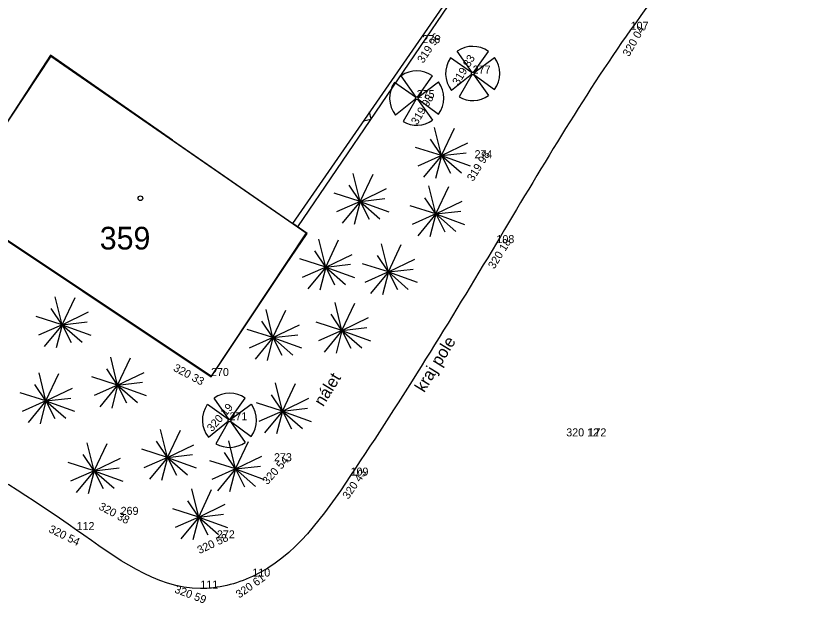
# Model space of a CAD drawing. Extents: x -742884 to -742543, y -1054677 to -1054433.
# Drawn here: x -742676.68 to -742647.31, y -1054570.62 to -1054548.61 of the extents above; entities that cross this region are included whole.
import ezdxf

# ---------------------------------------------------------------- set-up
doc = ezdxf.new("R2010")
doc.units = 0
for name, color, linetype in [('Vrstva 1', 7, 'Continuous'), ('Vrstva 10', 7, 'Continuous'), ('Vrstva 11', 7, 'Continuous'), ('Vrstva 15', 7, 'Continuous'), ('Vrstva 2', 7, 'Continuous'), ('Vrstva 3', 7, 'Continuous'), ('Vrstva 5', 7, 'Continuous'), ('Vrstva 50', 7, 'Continuous'), ('Vrstva 6', 7, 'Continuous')]:
    doc.layers.add(name, color=color, linetype=linetype)

# ---------------------------------------------------------------- blocks, each defined once
blk = doc.blocks.new('Z15')
at = {"layer": 'Vrstva 2'}
for p, q in [((-10, 2), (-8, 6)), ((-10, -2), (-10, 2)), ((-8, 6), (-6, 8)), ((-6, 8), (-2, 10)), ((-2, 10), (2, 10)), ((2, 10), (6, 8)), ((6, 8), (8, 6)), ((8, 6), (10, 2)), ((10, 2), (10, -2)), ((-8, -6), (-10, -2)), ((-6, -8), (-8, -6)), ((-2, -10), (-6, -8)), ((2, -10), (-2, -10)), ((6, -8), (2, -10)), ((8, -6), (6, -8)), ((10, -2), (8, -6))]:
    blk.add_line(p, q, dxfattribs=at)

msp = doc.modelspace()

# ---------------------------------------------------------------- linework, layer by layer
at = {"layer": 'Vrstva 1'}
for p, q in [((-742653.63, -1054549.14), (-742653.63, -1054549.14)), ((-742661.44, -1054549.64), (-742661.44, -1054549.64)), ((-742659.55, -1054550.78), (-742659.55, -1054550.78)), ((-742661.65, -1054551.7), (-742661.65, -1054551.7)), ((-742659.48, -1054553.95), (-742659.48, -1054553.95)), ((-742658.66, -1054557.13), (-742658.66, -1054557.13)), ((-742669.36, -1054562.11), (-742669.36, -1054562.11)), ((-742668.67, -1054563.77), (-742668.67, -1054563.77)), ((-742655.21, -1054564.37), (-742655.21, -1054564.37)), ((-742667, -1054565.3), (-742667, -1054565.3)), ((-742664.13, -1054565.84), (-742664.13, -1054565.84)), ((-742672.75, -1054567.31), (-742672.75, -1054567.31)), ((-742674.4, -1054567.88), (-742674.4, -1054567.88)), ((-742669.14, -1054568.19), (-742669.14, -1054568.19)), ((-742667.81, -1054569.62), (-742667.81, -1054569.62)), ((-742669.76, -1054570.07), (-742669.76, -1054570.07))]:
    msp.add_line(p, q, dxfattribs=at)
at = {"layer": 'Vrstva 10'}
for p, q in [((-742659.574, -1054550.74), (-742660.128, -1054549.943)), ((-742659.52, -1054550.74), (-742658.959, -1054549.949)), ((-742659.59, -1054550.746), (-742660.378, -1054550.19)), ((-742659.512, -1054550.751), (-742658.732, -1054550.174)), ((-742659.591, -1054550.815), (-742660.34, -1054551.417)), ((-742659.58, -1054550.825), (-742660.061, -1054551.656)), ((-742659.516, -1054550.82), (-742658.958, -1054551.607)), ((-742659.506, -1054550.809), (-742658.732, -1054551.382)), ((-742661.69, -1054551.666), (-742662.478, -1054551.11)), ((-742661.674, -1054551.66), (-742662.228, -1054550.863)), ((-742661.62, -1054551.66), (-742661.059, -1054550.869)), ((-742661.612, -1054551.671), (-742660.832, -1054551.094)), ((-742661.691, -1054551.735), (-742662.44, -1054552.337)), ((-742661.616, -1054551.74), (-742661.058, -1054552.527)), ((-742661.606, -1054551.729), (-742660.832, -1054552.302)), ((-742661.68, -1054551.745), (-742662.161, -1054552.576)), ((-742660.722, -1054553.85), (-742660.979, -1054552.8)), ((-742660.722, -1054553.85), (-742660.237, -1054552.825)), ((-742660.722, -1054553.85), (-742661.132, -1054553.239)), ((-742660.722, -1054553.85), (-742659.73, -1054553.371)), ((-742660.722, -1054553.85), (-742661.691, -1054553.543)), ((-742660.722, -1054553.85), (-742659.79, -1054553.744)), ((-742660.722, -1054553.85), (-742661.607, -1054554.243)), ((-742660.722, -1054553.85), (-742661.392, -1054554.664)), ((-742660.722, -1054553.85), (-742660.942, -1054554.709)), ((-742660.726, -1054553.844), (-742660.726, -1054553.844)), ((-742660.722, -1054553.85), (-742660.722, -1054553.85)), ((-742660.722, -1054553.85), (-742660.386, -1054554.514)), ((-742660.722, -1054553.85), (-742659.647, -1054554.239)), ((-742660.722, -1054553.85), (-742659.976, -1054554.503)), ((-742660.722, -1054553.85), (-742660.722, -1054553.85)), ((-742663.772, -1054555.57), (-742664.029, -1054554.52)), ((-742663.772, -1054555.57), (-742663.287, -1054554.545)), ((-742663.772, -1054555.57), (-742664.182, -1054554.959)), ((-742663.772, -1054555.57), (-742664.741, -1054555.263)), ((-742663.772, -1054555.57), (-742662.78, -1054555.091)), ((-742660.932, -1054556.04), (-742661.189, -1054554.99)), ((-742660.932, -1054556.04), (-742660.447, -1054555.015)), ((-742663.772, -1054555.57), (-742662.84, -1054555.464)), ((-742660.932, -1054556.04), (-742661.342, -1054555.429)), ((-742660.932, -1054556.04), (-742659.94, -1054555.561)), ((-742663.772, -1054555.57), (-742664.657, -1054555.963)), ((-742663.772, -1054555.57), (-742664.442, -1054556.384)), ((-742663.772, -1054555.57), (-742663.992, -1054556.429)), ((-742663.776, -1054555.564), (-742663.776, -1054555.564)), ((-742663.772, -1054555.57), (-742663.772, -1054555.57)), ((-742663.772, -1054555.57), (-742663.436, -1054556.234)), ((-742663.772, -1054555.57), (-742662.697, -1054555.959)), ((-742663.772, -1054555.57), (-742663.026, -1054556.223)), ((-742663.772, -1054555.57), (-742663.772, -1054555.57)), ((-742660.932, -1054556.04), (-742661.901, -1054555.733)), ((-742660.932, -1054556.04), (-742661.817, -1054556.433)), ((-742660.932, -1054556.04), (-742661.602, -1054556.854)), ((-742660.932, -1054556.04), (-742661.152, -1054556.899)), ((-742660.936, -1054556.034), (-742660.936, -1054556.034)), ((-742660.932, -1054556.04), (-742660, -1054555.934)), ((-742660.932, -1054556.04), (-742660.932, -1054556.04)), ((-742660.932, -1054556.04), (-742660.596, -1054556.704)), ((-742660.932, -1054556.04), (-742659.857, -1054556.429)), ((-742660.932, -1054556.04), (-742660.186, -1054556.693)), ((-742660.932, -1054556.04), (-742660.932, -1054556.04)), ((-742665.062, -1054558.03), (-742665.319, -1054556.98)), ((-742665.062, -1054558.03), (-742664.577, -1054557.005)), ((-742662.712, -1054558.21), (-742662.969, -1054557.16)), ((-742662.712, -1054558.21), (-742662.227, -1054557.185)), ((-742665.062, -1054558.03), (-742665.472, -1054557.419)), ((-742665.062, -1054558.03), (-742664.07, -1054557.551)), ((-742662.712, -1054558.21), (-742663.122, -1054557.599)), ((-742665.062, -1054558.03), (-742666.031, -1054557.723)), ((-742662.712, -1054558.21), (-742663.681, -1054557.903)), ((-742662.712, -1054558.21), (-742661.72, -1054557.731)), ((-742665.062, -1054558.03), (-742665.947, -1054558.423)), ((-742665.062, -1054558.03), (-742665.732, -1054558.844)), ((-742665.062, -1054558.03), (-742665.282, -1054558.889)), ((-742665.066, -1054558.024), (-742665.066, -1054558.024)), ((-742665.062, -1054558.03), (-742664.13, -1054557.924)), ((-742665.062, -1054558.03), (-742665.062, -1054558.03)), ((-742665.062, -1054558.03), (-742664.726, -1054558.694)), ((-742665.062, -1054558.03), (-742663.987, -1054558.419)), ((-742665.062, -1054558.03), (-742664.316, -1054558.683)), ((-742665.062, -1054558.03), (-742665.062, -1054558.03)), ((-742662.716, -1054558.204), (-742662.716, -1054558.204)), ((-742662.712, -1054558.21), (-742661.78, -1054558.104)), ((-742662.712, -1054558.21), (-742663.597, -1054558.603)), ((-742662.712, -1054558.21), (-742663.382, -1054559.024)), ((-742662.712, -1054558.21), (-742662.932, -1054559.069)), ((-742662.712, -1054558.21), (-742662.712, -1054558.21)), ((-742662.712, -1054558.21), (-742662.376, -1054558.874)), ((-742662.712, -1054558.21), (-742661.637, -1054558.599)), ((-742662.712, -1054558.21), (-742661.966, -1054558.863)), ((-742662.712, -1054558.21), (-742662.712, -1054558.21)), ((-742674.942, -1054560.19), (-742675.199, -1054559.14)), ((-742674.942, -1054560.19), (-742674.457, -1054559.165)), ((-742664.452, -1054560.4), (-742664.709, -1054559.35)), ((-742664.452, -1054560.4), (-742663.967, -1054559.375)), ((-742674.942, -1054560.19), (-742675.352, -1054559.579)), ((-742667.042, -1054560.67), (-742667.299, -1054559.62)), ((-742667.042, -1054560.67), (-742666.557, -1054559.645)), ((-742674.942, -1054560.19), (-742675.911, -1054559.883)), ((-742674.942, -1054560.19), (-742673.95, -1054559.711)), ((-742664.452, -1054560.4), (-742664.862, -1054559.789)), ((-742664.452, -1054560.4), (-742663.46, -1054559.921)), ((-742674.942, -1054560.19), (-742675.827, -1054560.583)), ((-742674.942, -1054560.19), (-742675.612, -1054561.004)), ((-742674.942, -1054560.19), (-742675.162, -1054561.049)), ((-742674.946, -1054560.184), (-742674.946, -1054560.184)), ((-742674.942, -1054560.19), (-742674.01, -1054560.084)), ((-742674.942, -1054560.19), (-742674.942, -1054560.19)), ((-742674.942, -1054560.19), (-742674.606, -1054560.854)), ((-742674.942, -1054560.19), (-742673.867, -1054560.579)), ((-742674.942, -1054560.19), (-742674.196, -1054560.843)), ((-742674.942, -1054560.19), (-742674.942, -1054560.19)), ((-742667.042, -1054560.67), (-742667.452, -1054560.059)), ((-742667.042, -1054560.67), (-742666.05, -1054560.191)), ((-742664.452, -1054560.4), (-742665.421, -1054560.093)), ((-742667.042, -1054560.67), (-742668.011, -1054560.363)), ((-742664.452, -1054560.4), (-742665.337, -1054560.793)), ((-742664.452, -1054560.4), (-742665.122, -1054561.214)), ((-742664.452, -1054560.4), (-742664.672, -1054561.259)), ((-742664.456, -1054560.394), (-742664.456, -1054560.394)), ((-742664.452, -1054560.4), (-742663.52, -1054560.294)), ((-742664.452, -1054560.4), (-742664.452, -1054560.4)), ((-742664.452, -1054560.4), (-742664.116, -1054561.064)), ((-742664.452, -1054560.4), (-742663.377, -1054560.789)), ((-742664.452, -1054560.4), (-742663.706, -1054561.053)), ((-742664.452, -1054560.4), (-742664.452, -1054560.4)), ((-742667.042, -1054560.67), (-742667.927, -1054561.063)), ((-742667.042, -1054560.67), (-742667.712, -1054561.484)), ((-742667.042, -1054560.67), (-742667.262, -1054561.529)), ((-742667.046, -1054560.664), (-742667.046, -1054560.664)), ((-742667.042, -1054560.67), (-742666.11, -1054560.564)), ((-742667.042, -1054560.67), (-742667.042, -1054560.67)), ((-742667.042, -1054560.67), (-742666.706, -1054561.334)), ((-742667.042, -1054560.67), (-742665.967, -1054561.059)), ((-742667.042, -1054560.67), (-742666.296, -1054561.323)), ((-742667.042, -1054560.67), (-742667.042, -1054560.67)), ((-742672.862, -1054562.45), (-742673.119, -1054561.4)), ((-742672.862, -1054562.45), (-742672.377, -1054561.425)), ((-742675.552, -1054563.04), (-742675.809, -1054561.99)), ((-742675.552, -1054563.04), (-742675.067, -1054562.015)), ((-742672.862, -1054562.45), (-742673.272, -1054561.839)), ((-742672.862, -1054562.45), (-742671.87, -1054561.971)), ((-742672.862, -1054562.45), (-742673.831, -1054562.143)), ((-742675.552, -1054563.04), (-742675.962, -1054562.429)), ((-742675.552, -1054563.04), (-742674.56, -1054562.561)), ((-742672.862, -1054562.45), (-742673.747, -1054562.843)), ((-742672.862, -1054562.45), (-742673.532, -1054563.264)), ((-742672.862, -1054562.45), (-742673.082, -1054563.309)), ((-742672.866, -1054562.444), (-742672.866, -1054562.444)), ((-742672.862, -1054562.45), (-742671.93, -1054562.344)), ((-742672.862, -1054562.45), (-742672.862, -1054562.45)), ((-742672.862, -1054562.45), (-742672.526, -1054563.114)), ((-742672.862, -1054562.45), (-742671.787, -1054562.839)), ((-742672.862, -1054562.45), (-742672.116, -1054563.103)), ((-742672.862, -1054562.45), (-742672.862, -1054562.45)), ((-742666.682, -1054563.42), (-742666.939, -1054562.37)), ((-742666.682, -1054563.42), (-742666.197, -1054562.395)), ((-742675.552, -1054563.04), (-742676.521, -1054562.733)), ((-742666.682, -1054563.42), (-742667.092, -1054562.809)), ((-742675.552, -1054563.04), (-742676.437, -1054563.433)), ((-742675.552, -1054563.04), (-742676.222, -1054563.854)), ((-742675.552, -1054563.04), (-742675.772, -1054563.899)), ((-742675.556, -1054563.034), (-742675.556, -1054563.034)), ((-742675.552, -1054563.04), (-742674.62, -1054562.934)), ((-742675.552, -1054563.04), (-742675.552, -1054563.04)), ((-742675.552, -1054563.04), (-742675.216, -1054563.704)), ((-742675.552, -1054563.04), (-742674.477, -1054563.429)), ((-742675.552, -1054563.04), (-742674.806, -1054563.693)), ((-742675.552, -1054563.04), (-742675.552, -1054563.04)), ((-742668.71, -1054563.736), (-742669.498, -1054563.18)), ((-742668.694, -1054563.73), (-742669.248, -1054562.933)), ((-742668.64, -1054563.73), (-742668.079, -1054562.939)), ((-742668.632, -1054563.741), (-742667.852, -1054563.164)), ((-742666.682, -1054563.42), (-742667.651, -1054563.113)), ((-742666.682, -1054563.42), (-742665.69, -1054562.941)), ((-742666.682, -1054563.42), (-742667.567, -1054563.813)), ((-742666.682, -1054563.42), (-742667.352, -1054564.234)), ((-742666.682, -1054563.42), (-742666.902, -1054564.279)), ((-742666.686, -1054563.414), (-742666.686, -1054563.414)), ((-742666.682, -1054563.42), (-742665.75, -1054563.314)), ((-742666.682, -1054563.42), (-742666.682, -1054563.42)), ((-742666.682, -1054563.42), (-742666.346, -1054564.084)), ((-742666.682, -1054563.42), (-742665.607, -1054563.809)), ((-742666.682, -1054563.42), (-742665.936, -1054564.073)), ((-742666.682, -1054563.42), (-742666.682, -1054563.42)), ((-742668.711, -1054563.805), (-742669.46, -1054564.407)), ((-742668.7, -1054563.815), (-742669.181, -1054564.646)), ((-742668.636, -1054563.81), (-742668.078, -1054564.597)), ((-742668.626, -1054563.799), (-742667.852, -1054564.372)), ((-742670.992, -1054565.16), (-742671.249, -1054564.11)), ((-742670.992, -1054565.16), (-742670.507, -1054564.135)), ((-742673.742, -1054565.66), (-742673.999, -1054564.61)), ((-742673.742, -1054565.66), (-742673.257, -1054564.635)), ((-742670.992, -1054565.16), (-742671.402, -1054564.549)), ((-742668.442, -1054565.59), (-742668.699, -1054564.54)), ((-742668.442, -1054565.59), (-742667.957, -1054564.565)), ((-742670.992, -1054565.16), (-742671.961, -1054564.853)), ((-742670.992, -1054565.16), (-742670, -1054564.681)), ((-742673.742, -1054565.66), (-742674.152, -1054565.049)), ((-742673.742, -1054565.66), (-742672.75, -1054565.181)), ((-742670.992, -1054565.16), (-742671.877, -1054565.553)), ((-742670.992, -1054565.16), (-742671.662, -1054565.974)), ((-742670.992, -1054565.16), (-742671.212, -1054566.019)), ((-742670.996, -1054565.154), (-742670.996, -1054565.154)), ((-742670.992, -1054565.16), (-742670.06, -1054565.054)), ((-742670.992, -1054565.16), (-742670.992, -1054565.16)), ((-742670.992, -1054565.16), (-742670.656, -1054565.824)), ((-742670.992, -1054565.16), (-742669.917, -1054565.549)), ((-742670.992, -1054565.16), (-742670.246, -1054565.813)), ((-742670.992, -1054565.16), (-742670.992, -1054565.16)), ((-742668.442, -1054565.59), (-742668.852, -1054564.979)), ((-742668.442, -1054565.59), (-742667.45, -1054565.111)), ((-742673.742, -1054565.66), (-742674.711, -1054565.353)), ((-742668.442, -1054565.59), (-742669.411, -1054565.283)), ((-742668.442, -1054565.59), (-742667.51, -1054565.484)), ((-742673.742, -1054565.66), (-742674.627, -1054566.053)), ((-742673.742, -1054565.66), (-742674.412, -1054566.474)), ((-742673.742, -1054565.66), (-742673.962, -1054566.519)), ((-742673.746, -1054565.654), (-742673.746, -1054565.654)), ((-742673.742, -1054565.66), (-742672.81, -1054565.554)), ((-742673.742, -1054565.66), (-742673.742, -1054565.66)), ((-742673.742, -1054565.66), (-742673.406, -1054566.324)), ((-742673.742, -1054565.66), (-742672.667, -1054566.049)), ((-742673.742, -1054565.66), (-742672.996, -1054566.313)), ((-742673.742, -1054565.66), (-742673.742, -1054565.66)), ((-742668.442, -1054565.59), (-742669.327, -1054565.983)), ((-742668.442, -1054565.59), (-742669.112, -1054566.404)), ((-742668.442, -1054565.59), (-742668.662, -1054566.449)), ((-742668.446, -1054565.584), (-742668.446, -1054565.584)), ((-742668.442, -1054565.59), (-742668.442, -1054565.59)), ((-742668.442, -1054565.59), (-742668.106, -1054566.254)), ((-742668.442, -1054565.59), (-742667.367, -1054565.979)), ((-742668.442, -1054565.59), (-742667.696, -1054566.243)), ((-742668.442, -1054565.59), (-742668.442, -1054565.59)), ((-742669.822, -1054567.39), (-742670.079, -1054566.34)), ((-742669.822, -1054567.39), (-742669.337, -1054566.365)), ((-742669.822, -1054567.39), (-742670.232, -1054566.779)), ((-742669.822, -1054567.39), (-742668.83, -1054566.911)), ((-742669.822, -1054567.39), (-742670.791, -1054567.083)), ((-742669.822, -1054567.39), (-742668.89, -1054567.284)), ((-742669.822, -1054567.39), (-742670.707, -1054567.783)), ((-742669.822, -1054567.39), (-742670.492, -1054568.204)), ((-742669.822, -1054567.39), (-742670.042, -1054568.249)), ((-742669.826, -1054567.384), (-742669.826, -1054567.384)), ((-742669.822, -1054567.39), (-742669.822, -1054567.39)), ((-742669.822, -1054567.39), (-742669.486, -1054568.054)), ((-742669.822, -1054567.39), (-742668.747, -1054567.779)), ((-742669.822, -1054567.39), (-742669.076, -1054568.043)), ((-742669.822, -1054567.39), (-742669.822, -1054567.39))]:
    msp.add_line(p, q, dxfattribs=at)
for centre, start, end in [((-742659.548, -1054550.777), 54.7465, 124.8105), ((-742659.549, -1054550.775), 144.8767, 218.9336), ((-742659.548, -1054550.777), 323.4756, 36.2971), ((-742661.648, -1054551.697), 54.7465, 124.8105), ((-742661.649, -1054551.695), 144.8767, 218.9336), ((-742661.648, -1054551.697), 323.4756, 36.2971), ((-742659.548, -1054550.777), 239.6151, 305.4552), ((-742661.648, -1054551.697), 239.6151, 305.4552), ((-742668.668, -1054563.767), 54.7465, 124.8105), ((-742668.669, -1054563.765), 144.8767, 218.9336), ((-742668.668, -1054563.767), 323.4756, 36.2971), ((-742668.668, -1054563.767), 239.6151, 305.4552)]:
    msp.add_arc(centre, 1.016, start, end, dxfattribs=at)
at = {"layer": 'Vrstva 11'}
msp.add_spline([(-742641.45, -1054542), (-742646.08, -1054542.32), (-742650.28, -1054545.1), (-742653.63, -1054549.14), (-742658.66, -1054557.13), (-742664.13, -1054565.84), (-742667.81, -1054569.62), (-742669.76, -1054570.07), (-742674.4, -1054567.88), (-742684.66, -1054562.03), (-742693.02, -1054556.88), (-742694.43, -1054554.37), (-742693.99, -1054552.67), (-742684.52, -1054539.64), (-742677.51, -1054529.95), (-742676.26, -1054526.54), (-742677.27, -1054522.39), (-742681.19, -1054517.29), (-742689.28, -1054510.73), (-742697.86, -1054505.14), (-742704.02, -1054502.75), (-742713.11, -1054501.07), (-742723.98, -1054503.51), (-742736.77, -1054510.1), (-742745.39, -1054515.75), (-742752.81, -1054521.82), (-742762.72, -1054531.38), (-742770.54, -1054539.36), (-742775.54, -1054544.64)], degree=3, dxfattribs=at)
at = {"layer": 'Vrstva 5'}
for p, q in [((-742653.09, -1054537.35), (-742666.116, -1054556.522)), ((-742663.428, -1054552.216), (-742663.373, -1054552.485)), ((-742663.642, -1054552.545), (-742663.373, -1054552.485))]:
    msp.add_line(p, q, dxfattribs=at)
at = {"layer": 'Vrstva 50'}
for p, q in [((-742675.38, -1054550.09), (-742679.03, -1054555.7)), ((-742670.8, -1054553.27), (-742675.38, -1054550.09)), ((-742670.8, -1054553.27), (-742666.29, -1054556.4))]:
    msp.add_line(p, q, dxfattribs=at)
msp.add_lwpolyline([(-742670.45, -1054526.06), (-742684.78, -1054546.85), (-742687.08, -1054550.18), (-742679.03, -1054555.7), (-742669.36, -1054562.14), (-742666.55, -1054557.95), (-742665.76, -1054556.77), (-742666.29, -1054556.4), (-742653.11, -1054537.36), (-742666.64, -1054528.55)], dxfattribs=at)
msp.add_circle((-742672.008, -1054555.45), 0.0875, dxfattribs=at)
at = {"layer": 'Vrstva 6'}
for p, q in [((-742675.37, -1054550.134), (-742679.05, -1054555.67)), ((-742675.37, -1054550.134), (-742665.793, -1054556.745)), ((-742669.36, -1054562.11), (-742679.05, -1054555.67)), ((-742665.793, -1054556.745), (-742669.36, -1054562.11))]:
    msp.add_line(p, q, dxfattribs=at)

# ---------------------------------------------------------------- block references
at = {"layer": 'Vrstva 10', "xscale": 0.005079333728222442, "yscale": 0.005079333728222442, "rotation": -30.671756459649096}
for p in [(-742659.55, -1054550.78), (-742661.65, -1054551.7), (-742668.67, -1054563.77)]:
    msp.add_blockref('Z15', p, dxfattribs=at)

# ---------------------------------------------------------------- texts
at = {"layer": 'Vrstva 15'}
for s, height, p in [('kraj pole', 0.4538, (-742661.369, -1054562.753)), ('nálet', 0.4497, (-742665.156, -1054563.28))]:
    msp.add_text(s, height=height, rotation=58.3519, dxfattribs=at).set_placement(p)
at = {"layer": 'Vrstva 2'}
for s, p in [('107', (-742653.63, -1054549.14)), ('276', (-742661.44, -1054549.64)), ('277', (-742659.55, -1054550.78)), ('275', (-742661.65, -1054551.7)), ('274', (-742659.48, -1054553.95)), ('108', (-742658.66, -1054557.13)), ('270', (-742669.36, -1054562.11)), ('271', (-742668.67, -1054563.77)), ('172', (-742655.21, -1054564.37)), ('273', (-742667, -1054565.3)), ('109', (-742664.13, -1054565.84)), ('269', (-742672.75, -1054567.31)), ('112', (-742674.4, -1054567.88)), ('272', (-742669.14, -1054568.19)), ('110', (-742667.81, -1054569.62)), ('111', (-742669.76, -1054570.07))]:
    msp.add_text(s, height=0.3, dxfattribs=at).set_placement(p)
at = {"layer": 'Vrstva 3'}
for s, rotation, p in [('320 04 ', 60.2323, (-742653.692, -1054550.171)), ('319 96 ', 56.3892, (-742661.407, -1054550.414)), ('319 83 ', 58.7652, (-742660.085, -1054551.24)), ('319 98 ', 58.815, (-742661.632, -1054552.725)), ('319 98 ', 57.86, (-742659.536, -1054554.842)), ('320 18 ', 58.1666, (-742658.744, -1054558.124)), ('320 33 ', 331.9984, (-742670.802, -1054561.897)), ('320 19 ', 48.7782, (-742669.322, -1054564.218)), ('320 54 ', 47.9546, (-742667.249, -1054566.203)), ('320 43 ', 55.7289, (-742664.212, -1054566.747)), ('320 38 ', 331.8011, (-742673.597, -1054567.087)), ('320 54 ', 333.8356, (-742675.473, -1054567.942)), ('320 58 ', 25.0169, (-742669.794, -1054568.782)), ('320 61 ', 35.2343, (-742668.302, -1054570.447)), ('320 59 ', 339.495, (-742670.755, -1054570.214))]:
    msp.add_text(s, height=0.3, rotation=rotation, dxfattribs=at).set_placement(p)
msp.add_text('320 12 ', height=0.3, dxfattribs=at).set_placement((-742656.043, -1054564.37))
at = {"layer": 'Vrstva 50'}
msp.add_text('359', height=0.85, dxfattribs=at).set_placement((-742673.532, -1054557.37))

doc.saveas('drawing.dxf')
